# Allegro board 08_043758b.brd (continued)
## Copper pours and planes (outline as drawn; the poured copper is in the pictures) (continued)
VIN_5V_USB_POWER on TOP: 102.21,52.91 105.24,52.91 105.24,53.94 104.22,53.94 103.97,54.19 103.97,54.81 102.72,54.81 102.21,54.3 ; 1 cut-out
VIN_5V_USB_POWER on L8_PWR: 102.53,43 102.53,55.06 106.02,55.06 106.02,43
(no net) on TOP: 15.97,12.01 15.97,16.33 22.07,16.33 22.07,15.06 20.42,15.06 20.29,14.93 20.29,14.54 18.39,14.54 18.39,14.24 20.29,14.24 20.29,13.41 20.17,13.28 18.26,13.28 18.26,12.01 17.17,12.01 17.17,13.03 17.32,13.03 17.32,13.18 17.02,13.18 17.02,12.01
(no net) on TOP: 37.56,12.01 37.56,16.33 42.14,16.33 42.52,16.71 43.79,16.71 43.79,15.19 42.14,15.19 41.88,14.93 41.88,14.55 39.98,14.55 39.98,14.35 41.88,14.35 41.88,13.41 41.76,13.28 39.85,13.28 39.85,12.01 38.91,12.01 38.91,13.18 38.61,13.18 38.61,12.01
(no net) on TOP: 20.17,10.49 18.26,10.49 18.26,11.76 15.97,11.76 15.97,9.22 18.51,6.68 20.17,6.68 ; 2 cut-outs
(no net) on TOP: 39.34,6.68 37.56,8.46 37.56,11.76 39.85,11.76 39.85,10.49 41.76,10.49 41.76,9.62 39.93,9.62 39.93,9.22 41.76,9.22 41.76,6.68 ; 1 cut-out
1P3_SUPPLY_A on TOP (solid shape): 42.27,16.46 42.38,16.48 42.44,16.38 42.83,15.69 43.62,15.79 43.73,15.81 43.79,15.72 43.79,15.19 42.14,15.19 41.88,14.93 41.88,14.55 39.98,14.55 39.98,14.37 39.91,14.26 39.89,14.13 39.89,13.44 39.89,13.39 39.91,13.34 39.91,13.28 39.85,13.28 39.85,13.23 39.79,13.23 39.74,13.24 39.69,13.24 39,13.24 38.9,13.23 38.8,13.18 38.61,13.18 38.61,12.01 37.56,12.01 37.56,13.65 38.47,13.65 38.47,14.95 37.56,14.95 37.56,16.33 38.06,16.33 38.06,15.43 39.36,15.43 39.36,16.33 39.72,16.33 39.72,16.32 39.76,16.32 39.79,16.28 39.82,16.25 39.82,15.78 40.64,15.78 40.64,16.25 40.67,16.28 40.71,16.32 40.74,16.32 40.74,16.33 40.99,16.33 40.99,16.32 41.03,16.32 41.06,16.28 41.09,16.25 41.09,15.78 41.91,15.78 41.91,16.25 41.94,16.28 41.98,16.32 42.01,16.32 42.01,16.33 42.14,16.33
1P3_SUPPLY_A on L3_PWR: 32.68,10.61 32.68,22.68 36.17,22.68 36.17,36.78 31.22,41.73 26.14,41.73 24.1,43.77 24.1,50.62 38.07,50.62 38.07,40.96 45.69,33.34 45.69,10.61
1P3_SUPPLY_B on TOP (solid shape): 16.47,15.43 17.77,15.43 17.77,16.33 18.13,16.33 18.13,16.32 18.17,16.32 18.2,16.28 18.23,16.25 18.23,15.78 19.05,15.78 19.05,16.25 19.08,16.28 19.12,16.32 19.15,16.32 19.15,16.33 19.4,16.33 19.4,16.32 19.44,16.32 19.47,16.28 19.5,16.25 19.5,15.78 20.32,15.78 20.32,16.25 20.35,16.28 20.39,16.32 20.42,16.32 20.42,16.33 20.89,16.33 20.97,16.29 20.99,16.21 21.23,15.53 21.93,15.41 22.03,15.4 22.07,15.31 22.07,15.06 20.42,15.06 20.29,14.93 20.29,14.54 18.39,14.54 18.39,14.38 18.33,14.26 18.3,14.13 18.3,13.44 18.3,13.39 18.32,13.34 18.32,13.28 18.26,13.28 18.26,13.23 18.2,13.23 18.15,13.24 18.1,13.24 17.41,13.24 17.31,13.23 17.21,13.18 17.02,13.18 17.02,12.01 15.97,12.01 15.97,13.65 16.88,13.65 16.88,14.95 15.97,14.95 15.97,16.33 16.47,16.33
1P3_SUPPLY_B on L8_PWR: 11.4,13.79 11.4,59.19 34.26,59.19 34.26,48.71 34.9,48.71 34.9,41.09 19.66,41.09 19.66,21.41 27.28,21.41 27.28,14.74 21.43,14.74 20.48,13.79
1P8V_CLK on TOP: 44.55,15.19 47.22,15.19 47.47,15.44 48.49,15.44 48.49,16.33 47.98,16.84 44.55,16.84
1P8V_CLK on L6_SIG: 25.84,12.2 41.32,12.2 42.65,13.53 47.32,13.53 47.32,18.87 24.94,18.87 24.94,13.1
SYNC on TOP: 87.48,13.03 90.27,13.03 90.27,19.12 88.24,19.12 87.48,18.36 ; 1 cut-out
TX1A_N on TOP (solid shape): 22.51,30.06 22.72,29.91 22.98,29.85 23.1,29.85 23.1,29 21.09,29 20.48,29.61 20.48,30.06
TX1A_P on TOP (solid shape): 23.1,30.69 22.77,30.69 22.55,30.47 20.48,30.47 20.48,30.93 21.09,31.54 23.1,31.54
UNNAMED_2_ADM7160V2_I254_VIN on TOP: 50.26,15.57 51.03,15.57 51.53,15.06 53.31,15.06 53.31,17.85 50.52,17.85 50.52,16.71 50.26,16.46
UNNAMED_2_ADP2164_I29_EN on TOP: 91.29,20.01 94.46,20.01 94.46,21.16 91.29,21.16 ; 1 cut-out
UNNAMED_4_ICTPS51206_I44_VLDOIN on TOP: 38.58,52.52 39.6,52.52 39.85,52.27 39.85,51.64 41.63,51.64 41.63,52.4 41.3,52.73 38.58,52.73
UNNAMED_9_ADM1177_I23_SENSE on TOP: 88.24,63.19 88.24,58.49 91.67,58.49 91.67,63.19
UNNAMED_9_ADM1177_I23_VCC on TOP: 92.56,58.49 98.27,58.49 98.27,63.45 92.56,63.45
UNNAMED_9_ADP198_I329_VOUT on TOP: 103.35,43.51 103.35,38.94 104.75,38.94 104.75,42.75 103.99,43.51
UNNAMED_9_ADP198_I329_VOUT on BOTTOM: 102.97,36.97 105.26,36.97 105.26,41.48 103.35,41.48 103.35,39.44 102.97,39.44
UNNAMED_9_ADP2114_I196_SW1 on TOP: 90.08,43.13 90.08,42.56 88.36,40.84 85.44,40.84 85.44,43.13 ; 1 cut-out
UNNAMED_9_ADP2114_I196_SW3 on TOP: 85.44,45.29 85.44,49.1 86.84,49.1 86.84,47.57 88.45,47.57 89.78,46.24 90.08,46.24 90.08,45.29 89.44,45.29 89.44,46.34 88.93,46.34 88.93,45.29
UNNAMED_9_CAP_I163_N1 on TOP: 81.25,36.9 85.06,36.9 85.06,39.06 84.55,39.06 84.3,39.32 84.3,43.13 81.25,43.13
UNNAMED_9_CN5P3SHLD_I255_N6 on TOP: 105.51,29.98 105.51,32.46 106.02,32.97 106.02,36.52 105.76,36.78 105.76,41.54 108.5,41.54 108.5,38.1 107.56,38.1 106.81,37.79 106.5,37.04 106.81,36.29 107.56,35.98 108.5,35.98 108.5,33.35 107.56,33.35 106.81,33.04 106.5,32.29 106.81,31.54 107.56,31.23 108.49,31.23 108.49,30.17 108.3,29.98
UNNAMED_9_CN5P3SHLD_I256_N6 on TOP: 103.73,46.3 103.73,48.08 105.51,49.86 105.51,50.24 106,50.73 106,54.95 105.49,55.46 105.49,57.1 108.5,57.1 108.5,55.88 107.56,55.88 106.81,55.57 106.5,54.82 106.81,54.07 107.56,53.76 108.5,53.76 108.5,51.13 107.56,51.13 106.81,50.82 106.5,50.07 106.81,49.32 107.56,49.01 108.5,49.01 108.5,48.06 108.47,48.06 108.47,46.3
VTT_0P75 on TOP: 39.6,52.93 43.53,52.93 43.53,54.94 40.23,54.94 40.23,53.41 39.95,53.13 39.6,53.13
VTT_0P75 on BOTTOM: 44.17,58.62 44.17,55.7 43.66,55.19 42.01,55.19 42.01,52.88 42.61,52.27 44.31,52.27 44.71,51.87 44.71,46.07 52.22,46.07 52.22,47.47 46.72,47.47 46.72,52.02 49.07,52.02 49.7,51.38 52.17,51.38 52.17,53.87 49.92,53.87 49.22,53.17 48.35,53.17 46.82,54.7 46.82,56.08 46.84,56.08 46.84,57.1 49.63,57.1 49.88,56.84 55.09,56.84 55.09,57.86 54.33,58.62 50.39,58.62 49.5,59.51 45.06,59.51

Small or netless copper shapes (teardrops, artwork), in the pictures only: 2 on TOP, 1 on L3_PWR

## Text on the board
BOTTOM: SECONDARY SIDE
TOP: ADALM-PLUTO | PRIMARY SIDE | 08-043758 REV B Z
Ref Des/Assembly Top: K | A | ASSEMBLY NOTES: | 1. DS1 AND DS2 ARE RIGHT ANGLE LEDs
Ref Des/Silkscreen Top: K | A
DIMENSION: " " | SEE DETAIL A | -0.076 | -0.242 | 2.486 | 2.320 | 2.240 | .004 | 0 | 4.297 | R13.599 | 1.932 | 1.899 | 1.745 | 1.712 | 1.232 | 1.199 | 1.045 | 1.012 | R.191 | 0.0330 | (2PLCS) | 0.0165 | 0.0395 | 0.0790 | RADIUS | FULL | SCALE: NONE | DETAIL A | 0.1870 | EDGE | PCB | REF | ARRAY DIMENSIONS | BOARD DIMENSIONS | x2 | FIDUCIAL | TOOLING HOLE (4X) | MOLEX47590-0001_CUTOUT-DETAIL | DIA MAX | -1.074 | .860 | .984 | 1.109 | 3.223 | 2.730
PAGE_OUTLINE: B | AS PER ECR-064863 | 22NOV16 | MBANCISOR | CUSTOMER EVAL BOARD Z
User.15: PREPREG 2.98MILS | PREPREG 2.9MILS | CORE 3MILS | NOTE: ALL IMPEDANCE TOLERANCE +/-10% | LAYER | L1 | L5 | L6 | L10 | SE = SINGLE ENDED, DP = DIFFERENTIAL PAIR | 100 OHMS DP | IMPEDANCE | 50 OHMS SE | 40 OHMS SE | 90 OHMS DP | 80 OHMS DP | REFERENCE | L4,L7 | L2 | L4 | L9 | LINE WIDTH | 19MILS | 6.5MILS | 4MILS | 9MILS | 4.5MILS | 5.5MILS | 5MILS | SPACE | 7MILS | 6MILS | N/A | IMPEDANCE TABLE
User.17: L2 GND | 08-      -07
User.18: L3 PWR | 08-      -08
User.19: L4 GND | 08-      -09
User.20: L5 SIG | 08-      -10
User.22: L6 SIG | 08-      -11
User.23: L7 GND | 08-      -12
User.24: L8 PWR | 08-      -13
User.25: L9 GND | 08-      -14
User.45: FIGURE | SIZE | 8.0 | 10.0 | 20.0 | 28.0 | 45.0 | 25.0 | 50.0 | 90.0 | 126.0 | 34.0x26.0 | 51.0x24.0 | FINISHED HOLES IN MILS | ALL UNITS ARE IN MILS | PLATED | NON-PLATED | QTY | 592 | 784 | 15 | 10 | 22 | 18 | 2 | 12 | 1 | 8 | 4 | TOLERANCE/NOTES
